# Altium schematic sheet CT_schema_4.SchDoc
size 514 x 279 mm
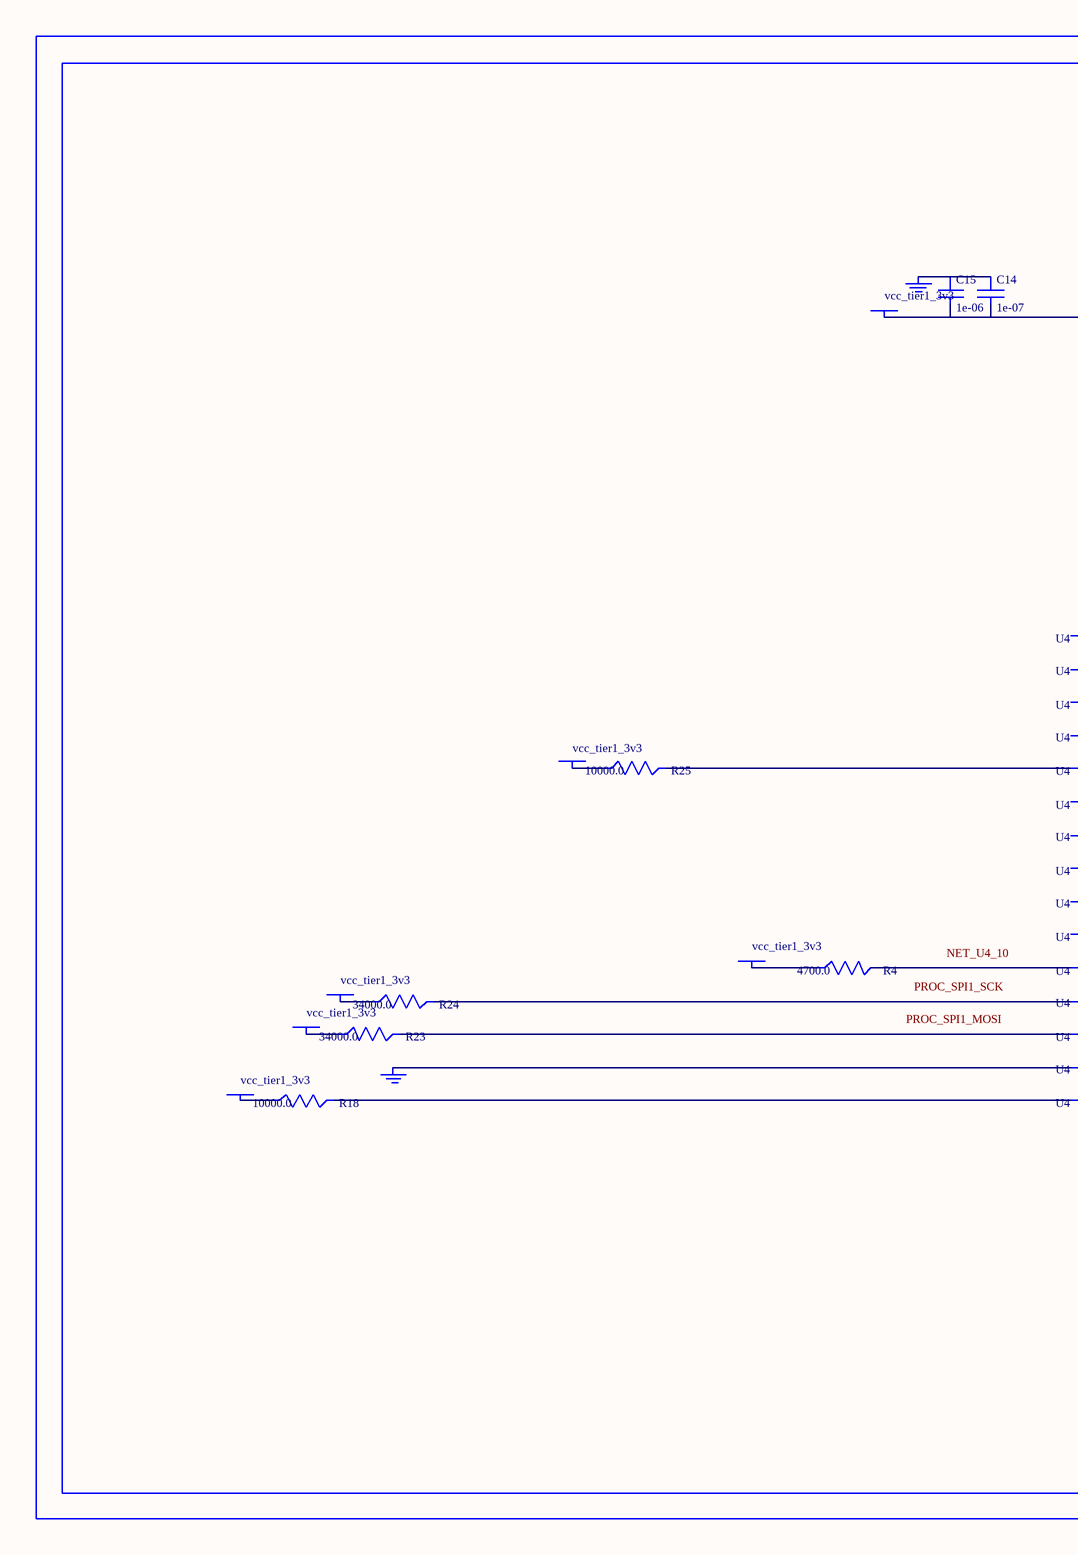
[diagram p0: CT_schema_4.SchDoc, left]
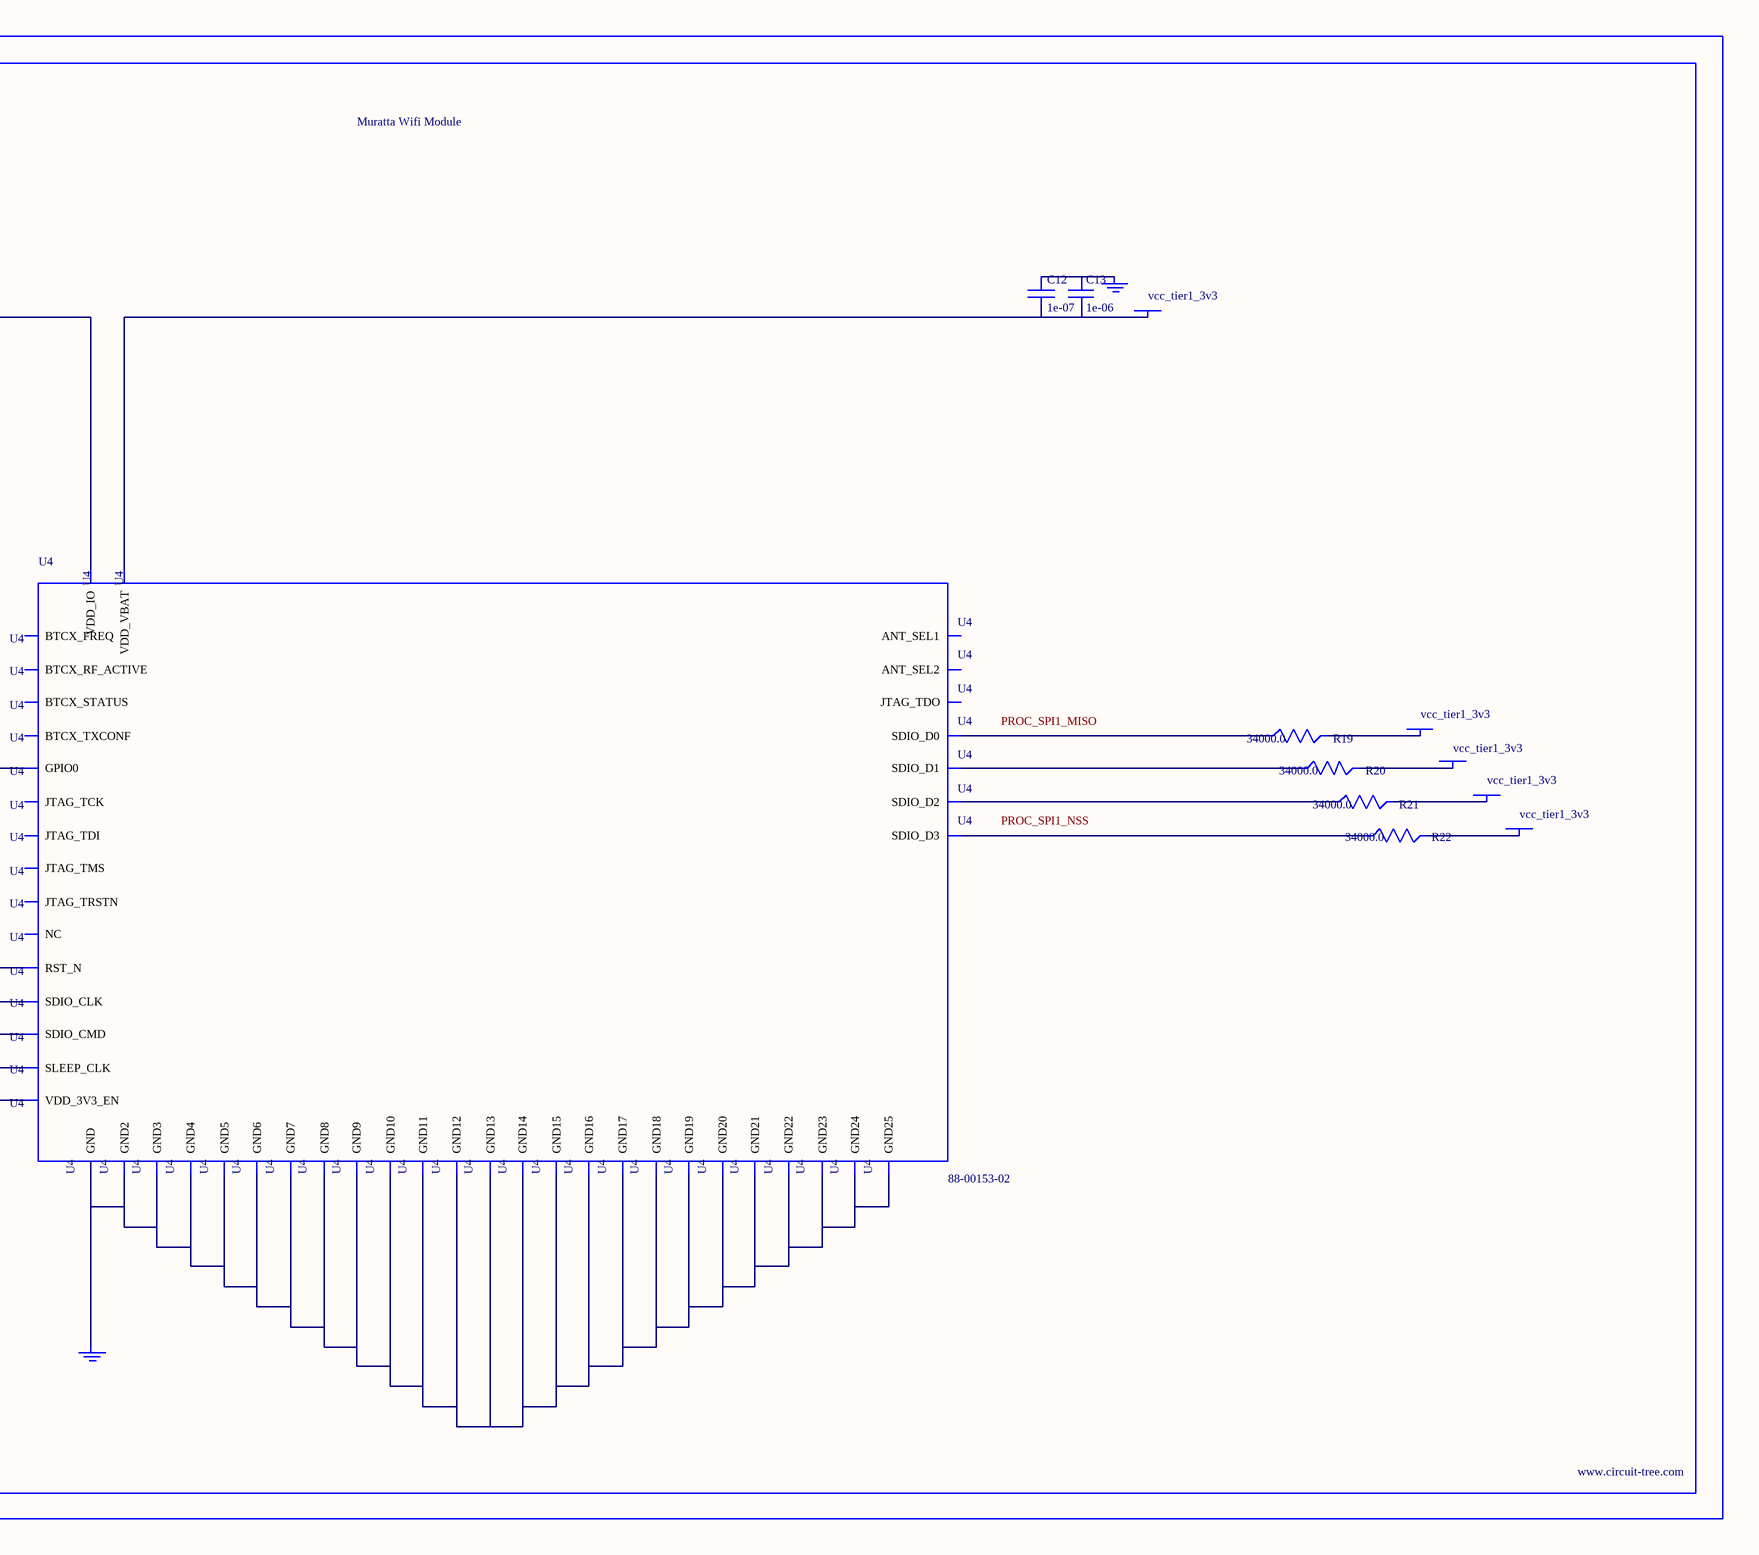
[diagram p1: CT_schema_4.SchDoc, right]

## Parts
BORDER3  (no value)
C12  1e-07  [C0402]
C13  1e-06  [C0603]
C14  1e-07  [C0402]
C15  1e-06  [C0603]
GND_INSTANCE_3_0  (no value)
GND_INSTANCE_3_1  (no value)
GND_INSTANCE_3_2  (no value)
GND_INSTANCE_3_3  (no value)
POWER_INSTANCE_3_0  vcc_tier1_3v3
POWER_INSTANCE_3_1  vcc_tier1_3v3
POWER_INSTANCE_3_2  vcc_tier1_3v3
POWER_INSTANCE_3_3  vcc_tier1_3v3
POWER_INSTANCE_3_4  vcc_tier1_3v3
POWER_INSTANCE_3_5  vcc_tier1_3v3
POWER_INSTANCE_3_6  vcc_tier1_3v3
POWER_INSTANCE_3_7  vcc_tier1_3v3
POWER_INSTANCE_3_8  vcc_tier1_3v3
POWER_INSTANCE_3_9  vcc_tier1_3v3
POWER_INSTANCE_3_10  vcc_tier1_3v3
R4  4700.0  [R0603]
R18  10000.0  [R0603]
R19  34000.0  [R0603]
R20  34000.0  [R0603]
R21  34000.0  [R0603]
R22  34000.0  [R0603]
R23  34000.0  [R0603]
R24  34000.0  [R0603]
R25  10000.0  [R0603]
U4  88-00153-02  [88-00153-02]

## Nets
NetC12_1: C12.1 C13.1 GND_INSTANCE_3_0.0(GND)
NetC12_2: C12.2 C13.2 POWER_INSTANCE_3_3.0(PWR) U4.12(VDD_VBAT)
NetC14_1: C14.1 C15.1 GND_INSTANCE_3_2.0(GND)
NetC14_2: C14.2 C15.2 POWER_INSTANCE_3_4.0(PWR) U4.33(VDD_IO)
NetGND_INSTANCE_3_1_0: GND_INSTANCE_3_1.0(GND) U4.31(SLEEP_CLK)
NetGND_INSTANCE_3_3_0: GND_INSTANCE_3_3.0(GND) U4.1(GND) U4.9(GND2) U4.13(GND3) U4.14(GND4) U4.15(GND5) U4.16(GND6) U4.17(GND7) U4.18(GND8) U4.19(GND9) U4.20(GND10) U4.21(GND11) U4.22(GND12) U4.23(GND13) U4.24(GND14) U4.25(GND15) U4.26(GND16) U4.27(GND17) U4.32(GND18) U4.39(GND19) U4.40(GND20) U4.41(GND21) U4.42(GND22) U4.43(GND23) U4.44(GND24) U4.49(GND25)
NetPOWER_INSTANCE_3_0_0: POWER_INSTANCE_3_0.0(PWR) R21.2
NetPOWER_INSTANCE_3_1_0: POWER_INSTANCE_3_1.0(PWR) R25.1
NetPOWER_INSTANCE_3_2_0: POWER_INSTANCE_3_2.0(PWR) R18.1
NetPOWER_INSTANCE_3_5_0: POWER_INSTANCE_3_5.0(PWR) R20.2
NetPOWER_INSTANCE_3_6_0: POWER_INSTANCE_3_6.0(PWR) R19.2
NetPOWER_INSTANCE_3_7_0: POWER_INSTANCE_3_7.0(PWR) R24.1
NetPOWER_INSTANCE_3_8_0: POWER_INSTANCE_3_8.0(PWR) R23.1
NetPOWER_INSTANCE_3_9_0: POWER_INSTANCE_3_9.0(PWR) R22.2
NetPOWER_INSTANCE_3_10_0: POWER_INSTANCE_3_10.0(PWR) R4.1
NetR4_2: R4.2 U4.10(RST_N)
NetR18_2: R18.2 U4.11(VDD_3V3_EN)
NetR19_1: R19.1 U4.35(SDIO_D0)
NetR20_1: R20.1 U4.34(SDIO_D1)
NetR21_1: R21.1 U4.2(SDIO_D2)
NetR22_1: R22.1 U4.38(SDIO_D3)
NetR23_2: R23.2 U4.37(SDIO_CMD)
NetR24_2: R24.2 U4.36(SDIO_CLK)
NetR25_2: R25.2 U4.6(GPIO0)

Not connected (* = marked no-connect by the designer): U4 3(JTAG_TDI) 4(JTAG_TDO) 5(BTCX_FREQ) 7(ANT_SEL2) 8(ANT_SEL1) 28(BTCX_STATUS) 29(BTCX_TXCONF) 30(BTCX_RF_ACTIVE) 45(JTAG_TCK) 46(JTAG_TRSTN) 47(JTAG_TMS) 48(NC)

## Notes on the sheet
- Labels drawn without touching a wire or pin: NET_U4_10, PROC_SPI1_MISO, PROC_SPI1_MOSI, PROC_SPI1_NSS, PROC_SPI1_SCK

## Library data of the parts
BORDER3 = BORDER_PAGE3
C12 C14 = C0402C104K3RACTU
C13 C15 = C0603C105K3RACTU
GND_INSTANCE_3_0-GND_INSTANCE_3_3 = GND
POWER_INSTANCE_3_0-POWER_INSTANCE_3_10 = PWR
R4 = RC0603JR-074K7L
R18 R25 = RC0603JR-0710KL
R19-R24 = ERA3ARB3402V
